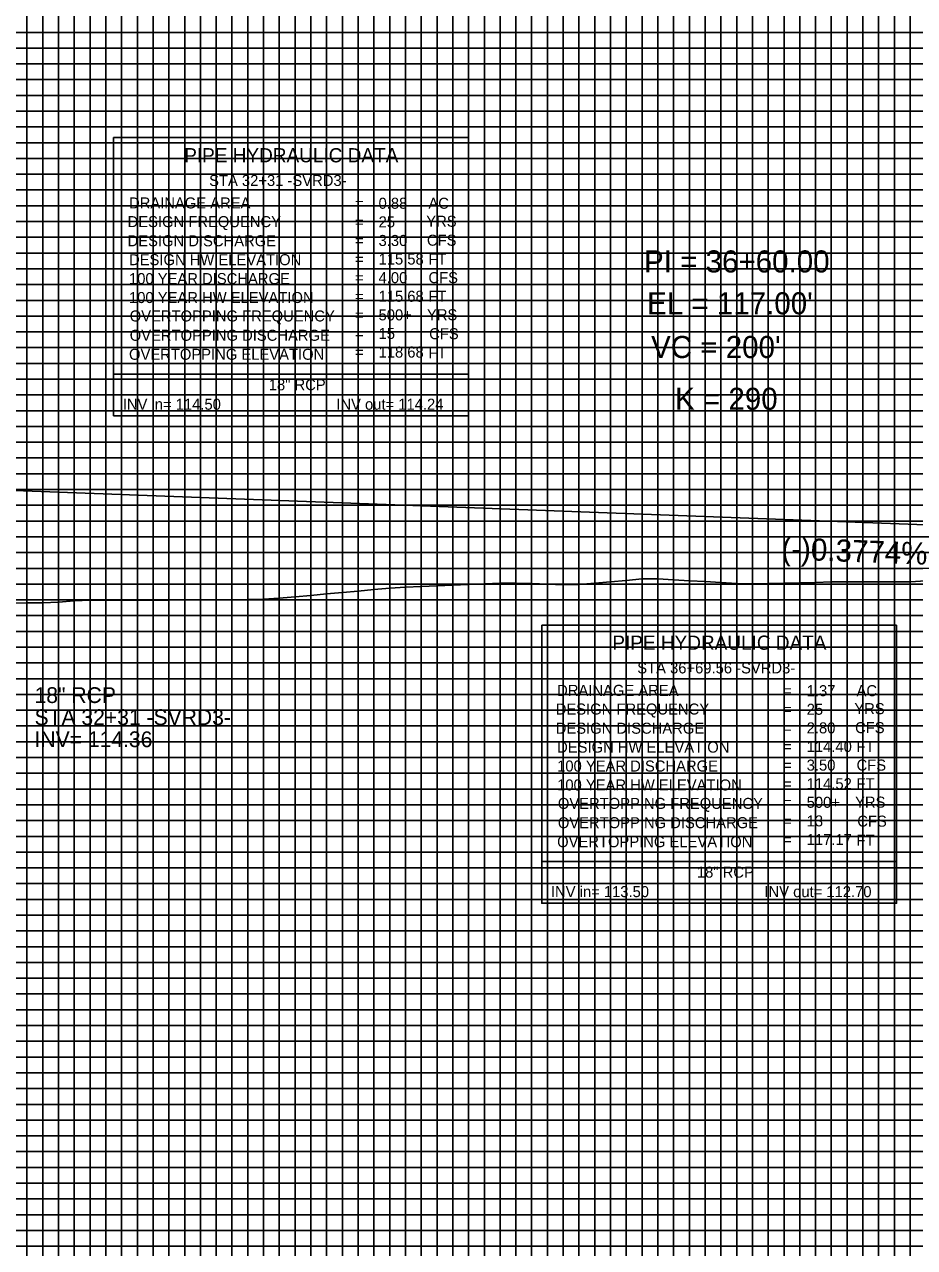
# Model space of a CAD drawing. Extents: x 2345490 to 2436403, y 465165 to 573888.
# Drawn here: x 2384041 to 2384323.2, y 500752.4 to 501140.3 of the extents above; entities that cross this region are included whole.
import ezdxf

# ---------------------------------------------------------------- set-up
doc = ezdxf.new("R2010")
doc.units = 0
for name, color, linetype in [('Old_Level_1', 7, 'Continuous'), ('Old_Level_2', 7, 'Continuous'), ('Old_Level_3', 7, 'Continuous'), ('Old_Level_4', 7, 'Continuous'), ('Old_Level_41', 7, 'Continuous'), ('Old_Level_42', 7, 'Continuous'), ('Old_Level_43', 7, 'Continuous'), ('Old_Level_57', 7, 'Continuous')]:
    doc.layers.add(name, color=color, linetype=linetype)

msp = doc.modelspace()

# ---------------------------------------------------------------- linework, layer by layer
at = {"layer": 'Old_Level_1'}
for points in [[(2384036.7988, 500956.76771), (2384041.7988, 500956.79467), (2384046.7988, 500956.82162), (2384051.7988, 500957.03035), (2384056.7988, 500957.44163), (2384061.7988, 500957.68441), (2384066.7988, 500957.69294), (2384071.7988, 500957.70148), (2384076.7988, 500957.71002), (2384081.7988, 500957.71855), (2384086.7988, 500957.72709), (2384091.7988, 500957.73563), (2384096.7988, 500957.74416), (2384101.7988, 500957.7527), (2384106.7988, 500957.80742), (2384111.7988, 500957.92083), (2384116.7988, 500958.03424), (2384121.7988, 500958.30507), (2384126.7988, 500958.75688), (2384131.7988, 500959.20869), (2384136.7988, 500959.6605), (2384141.7988, 500960.11232), (2384146.7988, 500960.56413), (2384151.7988, 500961.01594), (2384156.7988, 500961.46775), (2384161.7988, 500961.82), (2384166.7988, 500962.02769), (2384171.7988, 500962.23537), (2384176.7988, 500962.44306), (2384181.7988, 500962.65075), (2384186.7988, 500962.85843), (2384191.7988, 500963.06612), (2384196.7988, 500963.08497), (2384201.7988, 500962.91567), (2384206.7988, 500962.74636), (2384211.7988, 500962.57706), (2384216.7988, 500962.64181), (2384221.7988, 500963.08291), (2384226.7988, 500963.52401), (2384231.7988, 500963.96512), (2384236.7988, 500964.40622), (2384241.7988, 500964.42884), (2384246.7988, 500964.14545), (2384251.7988, 500963.86205), (2384256.7988, 500963.57866), (2384261.7988, 500963.29526), (2384266.7988, 500963.01187)], [(2384266.7988, 500963.01187), (2384271.7988, 500962.86592), (2384276.7988, 500962.98361), (2384281.7988, 500963.10131), (2384286.7988, 500963.219), (2384291.7988, 500963.3367), (2384296.7988, 500963.45439), (2384301.7988, 500963.50379), (2384306.7988, 500963.50871), (2384311.7988, 500963.51363), (2384316.7988, 500963.51855), (2384321.7988, 500963.52347), (2384326.7988, 500963.81003)]]:
    msp.add_lwpolyline(points, dxfattribs=at)
at = {"layer": 'Old_Level_2'}
msp.add_line((2383866.799, 500998.90725), (2384326.799, 500981.54875), dxfattribs=at)
at = {"layer": 'Old_Level_4'}
for p, q in [((2384069.25546, 501104.37046), (2384181.75546, 501104.37046)), ((2384069.25546, 501029.37046), (2384069.25546, 501104.37046)), ((2384181.75546, 501104.37046), (2384181.75546, 501029.37046)), ((2384181.75546, 501029.37046), (2384069.25546, 501029.37046)), ((2384204.97626, 500949.77522), (2384317.47626, 500949.77522)), ((2384204.97626, 500874.77522), (2384204.97626, 500949.77522)), ((2384317.47626, 500949.77522), (2384317.47626, 500874.77522)), ((2384317.47626, 500874.77522), (2384204.97626, 500874.77522))]:
    msp.add_line(p, q, dxfattribs=at)
for points in [[(2384069.25546, 501029.37046), (2384181.75546, 501029.37046), (2384181.75546, 501016.15546), (2384069.25546, 501016.15546)], [(2384204.97626, 500874.77522), (2384317.47626, 500874.77522), (2384317.47626, 500861.56022), (2384204.97626, 500861.56022)]]:
    msp.add_lwpolyline(points, close=True, dxfattribs=at)
at = {"layer": 'Old_Level_41'}
for points in [[(2384041.79875, 501632.775), (2384041.79875, 500607.775), (2384091.79875, 500607.775), (2384091.79875, 501632.775)], [(2384066.79875, 501632.775), (2384066.79875, 500607.775), (2384116.79875, 500607.775), (2384116.79875, 501632.775)], [(2384141.79875, 501632.775), (2384141.79875, 500607.775), (2384191.79875, 500607.775), (2384191.79875, 501632.775)], [(2384166.79875, 501632.775), (2384166.79875, 500607.775), (2384216.79875, 500607.775), (2384216.79875, 501632.775)], [(2384241.79875, 501632.775), (2384241.79875, 500607.775), (2384291.79875, 500607.775), (2384291.79875, 501632.775)], [(2384266.79875, 501632.775), (2384266.79875, 500607.775), (2384316.79875, 500607.775), (2384316.79875, 501632.775)], [(2384616.79875, 501132.775), (2383116.79875, 501132.775), (2383116.79875, 501082.775), (2384616.79875, 501082.775)], [(2384616.79875, 501032.775), (2383116.79875, 501032.775), (2383116.79875, 500982.775), (2384616.79875, 500982.775)], [(2384616.79875, 500957.775), (2383116.79875, 500957.775), (2383116.79875, 501007.775), (2384616.79875, 501007.775)], [(2384616.79875, 500932.775), (2383116.79875, 500932.775), (2383116.79875, 500882.775), (2384616.79875, 500882.775)], [(2384616.79875, 500857.775), (2383116.79875, 500857.775), (2383116.79875, 500907.775), (2384616.79875, 500907.775)], [(2384616.79875, 500832.775), (2383116.79875, 500832.775), (2383116.79875, 500782.775), (2384616.79875, 500782.775)]]:
    msp.add_lwpolyline(points, dxfattribs=at)
at = {"layer": 'Old_Level_42'}
for points in [[(2384616.79875, 501057.775), (2383116.79875, 501057.775), (2383116.79875, 501107.775), (2384616.79875, 501107.775)], [(2384616.79875, 500757.775), (2383116.79875, 500757.775), (2383116.79875, 500807.775), (2384616.79875, 500807.775)]]:
    msp.add_lwpolyline(points, dxfattribs=at)
at = {"layer": 'Old_Level_43'}
for points in [[(2384036.79875, 501632.775), (2384036.79875, 500607.775), (2384046.79875, 500607.775), (2384046.79875, 501632.775)], [(2384051.79875, 501632.775), (2384051.79875, 500607.775), (2384056.79875, 500607.775), (2384056.79875, 501632.775)], [(2384061.79875, 501632.775), (2384061.79875, 500607.775), (2384071.79875, 500607.775), (2384071.79875, 501632.775)], [(2384076.79875, 501632.775), (2384076.79875, 500607.775), (2384081.79875, 500607.775), (2384081.79875, 501632.775)], [(2384086.79875, 501632.775), (2384086.79875, 500607.775), (2384096.79875, 500607.775), (2384096.79875, 501632.775)], [(2384101.79875, 501632.775), (2384101.79875, 500607.775), (2384106.79875, 500607.775), (2384106.79875, 501632.775)], [(2384111.79875, 501632.775), (2384111.79875, 500607.775), (2384121.79875, 500607.775), (2384121.79875, 501632.775)], [(2384126.79875, 501632.775), (2384126.79875, 500607.775), (2384131.79875, 500607.775), (2384131.79875, 501632.775)], [(2384136.79875, 501632.775), (2384136.79875, 500607.775), (2384146.79875, 500607.775), (2384146.79875, 501632.775)], [(2384151.79875, 501632.775), (2384151.79875, 500607.775), (2384156.79875, 500607.775), (2384156.79875, 501632.775)], [(2384161.79875, 501632.775), (2384161.79875, 500607.775), (2384171.79875, 500607.775), (2384171.79875, 501632.775)], [(2384176.79875, 501632.775), (2384176.79875, 500607.775), (2384181.79875, 500607.775), (2384181.79875, 501632.775)], [(2384186.79875, 501632.775), (2384186.79875, 500607.775)], [(2384186.79875, 500607.775), (2384196.79875, 500607.775), (2384196.79875, 501632.775)], [(2384201.79875, 501632.775), (2384201.79875, 500607.775), (2384206.79875, 500607.775), (2384206.79875, 501632.775)], [(2384211.79875, 501632.775), (2384211.79875, 500607.775), (2384221.79875, 500607.775), (2384221.79875, 501632.775)], [(2384226.79875, 501632.775), (2384226.79875, 500607.775), (2384231.79875, 500607.775), (2384231.79875, 501632.775)], [(2384236.79875, 501632.775), (2384236.79875, 500607.775), (2384246.79875, 500607.775), (2384246.79875, 501632.775)], [(2384251.79875, 501632.775), (2384251.79875, 500607.775), (2384256.79875, 500607.775), (2384256.79875, 501632.775)], [(2384261.79875, 501632.775), (2384261.79875, 500607.775), (2384271.79875, 500607.775), (2384271.79875, 501632.775)], [(2384276.79875, 501632.775), (2384276.79875, 500607.775), (2384281.79875, 500607.775), (2384281.79875, 501632.775)], [(2384286.79875, 501632.775), (2384286.79875, 500607.775), (2384296.79875, 500607.775), (2384296.79875, 501632.775)], [(2384301.79875, 501632.775), (2384301.79875, 500607.775), (2384306.79875, 500607.775), (2384306.79875, 501632.775)], [(2384311.79875, 501632.775), (2384311.79875, 500607.775), (2384321.79875, 500607.775), (2384321.79875, 501632.775)], [(2384566.79875, 501137.775), (2383166.79875, 501137.775), (2383166.79875, 501127.775), (2384566.79875, 501127.775)], [(2384566.79875, 501122.775), (2383166.79875, 501122.775), (2383166.79875, 501117.775), (2384566.79875, 501117.775)], [(2384566.79875, 501112.775), (2383166.79875, 501112.775)], [(2383166.79875, 501102.775), (2384566.79875, 501102.775)], [(2384566.79875, 501097.775), (2383166.79875, 501097.775), (2383166.79875, 501092.775), (2384566.79875, 501092.775)], [(2384566.79875, 501087.775), (2383166.79875, 501087.775), (2383166.79875, 501077.775), (2384566.79875, 501077.775)], [(2384566.79875, 501072.775), (2383166.79875, 501072.775), (2383166.79875, 501067.775), (2384566.79875, 501067.775)], [(2384566.79875, 501062.775), (2383166.79875, 501062.775), (2383166.79875, 501052.775), (2384566.79875, 501052.775)], [(2384566.79875, 501047.775), (2383166.79875, 501047.775), (2383166.79875, 501042.775), (2384566.79875, 501042.775)], [(2384566.79875, 501037.775), (2383166.79875, 501037.775), (2383166.79875, 501027.775), (2384566.79875, 501027.775)], [(2384566.79875, 501022.775), (2383166.79875, 501022.775), (2383166.79875, 501017.775), (2384566.79875, 501017.775)], [(2384566.79875, 501012.775), (2383166.79875, 501012.775), (2383166.79875, 501002.775), (2384566.79875, 501002.775)], [(2384566.79875, 500997.775), (2383166.79875, 500997.775), (2383166.79875, 500992.775), (2384566.79875, 500992.775)], [(2384566.79875, 500987.775), (2383166.79875, 500987.775), (2383166.79875, 500977.775), (2384566.79875, 500977.775)], [(2384566.79875, 500972.775), (2383166.79875, 500972.775), (2383166.79875, 500967.775), (2384566.79875, 500967.775)], [(2384566.79875, 500962.775), (2383166.79875, 500962.775), (2383166.79875, 500952.775), (2384566.79875, 500952.775)], [(2384566.79875, 500947.775), (2383166.79875, 500947.775), (2383166.79875, 500942.775), (2384566.79875, 500942.775)], [(2384566.79875, 500937.775), (2383166.79875, 500937.775), (2383166.79875, 500927.775), (2384566.79875, 500927.775)], [(2384566.79875, 500922.775), (2383166.79875, 500922.775), (2383166.79875, 500917.775), (2384566.79875, 500917.775)], [(2384566.79875, 500912.775), (2383166.79875, 500912.775), (2383166.79875, 500902.775), (2384566.79875, 500902.775)], [(2384566.79875, 500897.775), (2383166.79875, 500897.775), (2383166.79875, 500892.775), (2384566.79875, 500892.775)], [(2384566.79875, 500887.775), (2383166.79875, 500887.775), (2383166.79875, 500877.775), (2384566.79875, 500877.775)], [(2384566.79875, 500872.775), (2383166.79875, 500872.775), (2383166.79875, 500867.775), (2384566.79875, 500867.775)], [(2384566.79875, 500862.775), (2383166.79875, 500862.775), (2383166.79875, 500852.775), (2384566.79875, 500852.775)], [(2384566.79875, 500847.775), (2383166.79875, 500847.775), (2383166.79875, 500842.775), (2384566.79875, 500842.775)], [(2384566.79875, 500837.775), (2383166.79875, 500837.775), (2383166.79875, 500827.775), (2384566.79875, 500827.775)], [(2384566.79875, 500822.775), (2383166.79875, 500822.775), (2383166.79875, 500817.775), (2384566.79875, 500817.775)], [(2384566.79875, 500812.775), (2383166.79875, 500812.775)], [(2383166.79875, 500802.775), (2384566.79875, 500802.775)], [(2384566.79875, 500797.775), (2383166.79875, 500797.775), (2383166.79875, 500792.775), (2384566.79875, 500792.775)], [(2384566.79875, 500787.775), (2383166.79875, 500787.775)], [(2383166.79875, 500777.775), (2384566.79875, 500777.775)], [(2384566.79875, 500772.775), (2383166.79875, 500772.775), (2383166.79875, 500767.775), (2384566.79875, 500767.775)], [(2384566.79875, 500762.775), (2383166.79875, 500762.775), (2383166.79875, 500752.775), (2384566.79875, 500752.775)]]:
    msp.add_lwpolyline(points, dxfattribs=at)
at = {"layer": 'Old_Level_57'}
for p, q in [((2381716.79925, 501057.77525), (2385066.79875, 501057.77525)), ((2384066.79875, 500607.77525), (2384066.79875, 501057.77525)), ((2384066.79875, 500607.87525), (2384066.79875, 501057.77525)), ((2384166.79875, 500607.77525), (2384166.79875, 501057.77525)), ((2384166.79875, 500607.87525), (2384166.79875, 501057.77525)), ((2384266.79875, 500607.77525), (2384266.79875, 501057.77525)), ((2384266.79875, 500607.87525), (2384266.79875, 501057.77525)), ((2381716.79925, 501007.77525), (2385066.79875, 501007.77525)), ((2381716.79925, 500957.77525), (2385066.79875, 500957.77525)), ((2381716.79925, 500907.77525), (2385066.79875, 500907.77525)), ((2381716.79925, 500857.77525), (2385066.79875, 500857.77525)), ((2381716.79925, 500807.77525), (2385066.79875, 500807.77525)), ((2381716.79925, 500757.77525), (2385066.79875, 500757.77525))]:
    msp.add_line(p, q, dxfattribs=at)

# ---------------------------------------------------------------- texts
at = {"layer": 'Old_Level_2'}
for s, height, p in [('PI = 36+60.00', 7.0000005, (2384237.43119, 501061.61781)), ("EL = 117.00'", 7.0000005, (2384238.38419, 501048.34906)), ("VC = 200'", 7.000001, (2384239.65219, 501034.47306)), ('K = 290', 7.000001, (2384247.26169, 501018.05306))]:
    msp.add_text(s, height=height, dxfattribs=at).set_placement(p)
msp.add_text('(-)0.3774%', height=7.000001, rotation=357.8389194, dxfattribs=at).set_placement((2384280.87, 500970.65675))
at = {"layer": 'Old_Level_3'}
for s, height, p in [('18" RCP', 4.999999, (2384044.20575, 500925.06725)), ('STA 32+31 -SVRD3-', 4.9999995, (2384044.20575, 500918.06725)), ('INV= 114.36', 4.9999995, (2384044.20575, 500911.06725))]:
    msp.add_text(s, height=height, dxfattribs=at).set_placement(p)
at = {"layer": 'Old_Level_4'}
for s, height, p in [('PIPE HYDRAULIC DATA', 4.49985, (2384091.65546, 501096.54546)), ('STA 32+31 -SVRD3-', 3.4998, (2384099.54921, 501089.04521)), ('DRAINAGE AREA', 3.49995, (2384074.15546, 501081.92046)), ('=        ', 3.49995, (2384145.80546, 501081.82046)), ('0.88', 3.49995, (2384153.26596, 501081.81996)), ('AC', 3.49995, (2384169.08046, 501081.82046)), ('DESIGN FREQUENCY', 3.49995, (2384073.70546, 501075.99546)), ('=        ', 3.49995, (2384145.80546, 501075.92046)), ('25', 3.49995, (2384153.26596, 501075.92021)), ('YRS', 3.49995, (2384168.38046, 501076.12046)), ('DESIGN DISCHARGE', 3.49995, (2384073.70546, 501069.92046)), ('=        ', 3.49995, (2384145.80546, 501070.02046)), ('3.30', 3.49995, (2384153.26596, 501070.02021)), ('CFS', 3.49995, (2384168.60546, 501070.09546)), ('DESIGN HW ELEVATION', 3.49995, (2384074.15546, 501063.92046)), ('=        ', 3.49995, (2384145.80546, 501064.12046)), ('115.58', 3.49995, (2384153.26596, 501064.12021)), ('FT', 3.49995, (2384169.08046, 501064.12046)), ('100 YEAR DISCHARGE', 3.49995, (2384074.15546, 501057.92046)), ('=        ', 3.49995, (2384145.80546, 501058.22046)), ('4.00', 3.49995, (2384153.26596, 501058.22021)), ('CFS', 3.49995, (2384169.08046, 501058.22046)), ('100 YEAR HW ELEVATION', 3.49995, (2384074.15546, 501051.92046)), ('=        ', 3.49995, (2384145.80546, 501052.32046)), ('115.68', 3.49995, (2384153.26596, 501052.32021)), ('FT', 3.49995, (2384169.08046, 501052.32046)), ('OVERTOPPING FREQUENCY', 3.49995, (2384074.38046, 501046.07046)), ('=        ', 3.49995, (2384145.80546, 501046.42046)), ('500+', 3.49995, (2384153.26596, 501046.42046)), ('YRS', 3.49995, (2384168.60546, 501046.47046)), ('OVERTOPPING DISCHARGE', 3.49995, (2384074.38046, 501039.94546)), ('=        ', 3.49995, (2384145.80546, 501040.52046)), ('15', 3.49995, (2384153.26596, 501040.52046)), ('CFS', 3.49995, (2384169.30546, 501040.44546)), ('OVERTOPPING ELEVATION', 3.49995, (2384074.15546, 501033.92046)), ('=        ', 3.49995, (2384145.80546, 501034.62046)), ('118.68', 3.49995, (2384153.26596, 501034.62046)), ('FT', 3.49995, (2384169.08046, 501034.42046)), ('18" RCP', 3.4998, (2384118.46121, 501024.26821)), ('INV in= 114.50', 3.4998, (2384072.18796, 501018.08246)), ('INV out= 114.24', 3.4998, (2384139.86471, 501018.08246)), ('PIPE HYDRAULIC DATA', 4.49985, (2384227.37626, 500941.95022)), ('STA 36+69.56 -SVRD3-', 3.4998, (2384235.27001, 500934.44997)), ('DRAINAGE AREA', 3.49995, (2384209.87626, 500927.32522)), ('=        ', 3.49995, (2384281.52626, 500927.22522)), ('1.37', 3.49995, (2384288.98676, 500927.22472)), ('AC', 3.49995, (2384304.80126, 500927.22522)), ('DESIGN FREQUENCY', 3.49995, (2384209.42626, 500921.40022)), ('25', 3.49995, (2384288.98676, 500921.32497)), ('YRS', 3.49995, (2384304.10126, 500921.52522)), ('=        ', 3.49995, (2384281.52626, 500921.32522)), ('DESIGN DISCHARGE', 3.49995, (2384209.42626, 500915.32522)), ('=        ', 3.49995, (2384281.52626, 500915.42522)), ('2.80', 3.49995, (2384288.98676, 500915.42497)), ('CFS', 3.49995, (2384304.32626, 500915.50022)), ('114.40', 3.49995, (2384288.98676, 500909.52497)), ('FT', 3.49995, (2384304.80126, 500909.52522)), ('DESIGN HW ELEVATION', 3.49995, (2384209.87626, 500909.32522)), ('=        ', 3.49995, (2384281.52626, 500909.52522)), ('100 YEAR DISCHARGE', 3.49995, (2384209.87626, 500903.32522)), ('=        ', 3.49995, (2384281.52626, 500903.62522)), ('3.50', 3.49995, (2384288.98676, 500903.62497)), ('CFS', 3.49995, (2384304.80126, 500903.62522)), ('114.52', 3.49995, (2384288.98676, 500897.72497)), ('100 YEAR HW ELEVATION', 3.49995, (2384209.87626, 500897.32522)), ('=        ', 3.49995, (2384281.52626, 500897.72522)), ('FT', 3.49995, (2384304.80126, 500897.72522)), ('OVERTOPPING FREQUENCY', 3.49995, (2384210.10126, 500891.47522)), ('=        ', 3.49995, (2384281.52626, 500891.82522)), ('500+', 3.49995, (2384288.98676, 500891.82522)), ('YRS', 3.49995, (2384304.32626, 500891.87522)), ('OVERTOPPING DISCHARGE', 3.49995, (2384210.10126, 500885.35022)), ('=        ', 3.49995, (2384281.52626, 500885.92522)), ('13', 3.49995, (2384288.98676, 500885.92522)), ('CFS', 3.49995, (2384305.02626, 500885.85022)), ('OVERTOPPING ELEVATION', 3.49995, (2384209.87626, 500879.32522)), ('=        ', 3.49995, (2384281.52626, 500880.02522)), ('117.17', 3.49995, (2384288.98676, 500880.02522)), ('FT', 3.49995, (2384304.80126, 500879.82522)), ('18" RCP', 3.4998, (2384254.18201, 500869.67297)), ('INV in= 113.50', 3.4998, (2384207.90876, 500863.48722)), ('INV out= 112.70', 3.4998, (2384275.58551, 500863.48722))]:
    msp.add_text(s, height=height, dxfattribs=at).set_placement(p)

doc.saveas('drawing.dxf')
